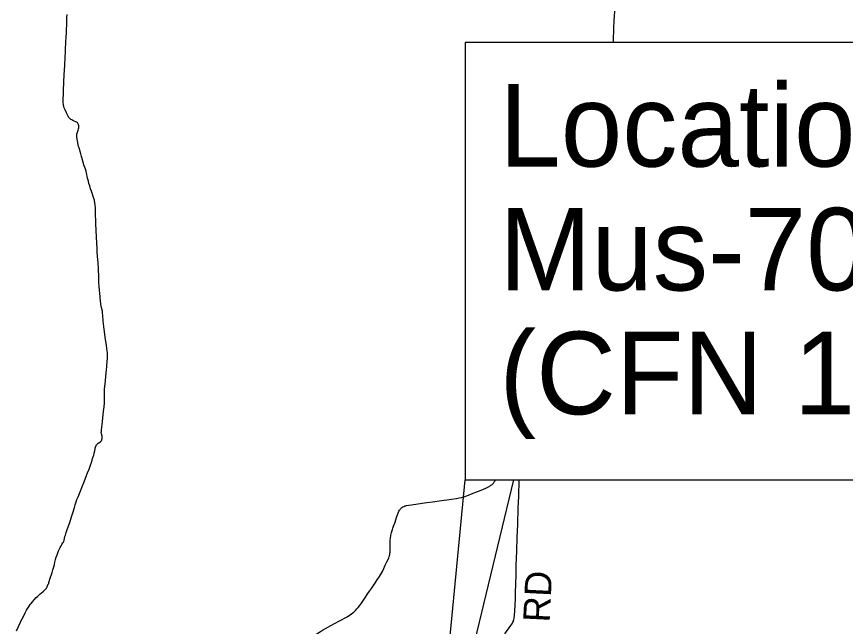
# Model space of a CAD drawing. Extents: x 1761803 to 2441803, y 509895 to 949895.
# Drawn here: x 2113045 to 2141149, y 814988 to 835674 of the extents above; entities that cross this region are included whole.
import ezdxf

# ---------------------------------------------------------------- set-up
doc = ezdxf.new("R2010")
doc.units = 0
for name, color, linetype in [('GM_X_County_Road', 7, 'Continuous'), ('GM_X_Minor_Lake', 7, 'Continuous'), ('GM_X_State_Location', 7, 'Continuous')]:
    doc.layers.add(name, color=color, linetype=linetype)

msp = doc.modelspace()

# ---------------------------------------------------------------- linework, layer by layer
at = {"layer": 'GM_X_County_Road'}
msp.add_lwpolyline([(2129600, 814737), (2129806, 815021), (2129835, 815061), (2129861, 815102), (2129876, 815131), (2129889, 815162), (2129899, 815193), (2129907, 815225), (2129916, 815273), (2129929, 815370), (2129941, 815501), (2129960, 815925), (2129967, 816089), (2129976, 816467), (2129981, 816693), (2129990, 817070), (2130007, 817544), (2130021, 818018), (2130038, 818440), (2130055, 819010), (2130065, 819195), (2130074, 819411), (2130090, 819951), (2130090, 819961)], dxfattribs=at)
at = {"layer": 'GM_X_Minor_Lake'}
for points in [[(2133281, 834796), (2133283, 834853), (2133300, 835280), (2133312, 835526), (2133327, 835852)], [(2114639, 833153), (2114640, 833174), (2114663, 833714), (2114676, 834009), (2114692, 834304), (2114699, 834464), (2114704, 834550), (2114718, 834812), (2114726, 834976), (2114733, 835123), (2114740, 835254), (2114744, 835368), (2114751, 835548), (2114754, 835646), (2114758, 835745)], [(2114248, 816818), (2114278, 816912), (2114307, 817009), (2114326, 817089), (2114347, 817171), (2114369, 817258), (2114393, 817341), (2114418, 817413), (2114442, 817481), (2114467, 817547), (2114488, 817598), (2114520, 817669), (2114552, 817726), (2114579, 817767), (2114617, 817821), (2114635, 817850), (2114644, 817874), (2114656, 817912), (2114686, 818037), (2114699, 818085), (2114727, 818171), (2114751, 818242), (2114763, 818275), (2114850, 818518), (2114906, 818705), (2114962, 818880), (2115008, 819021), (2115037, 819114), (2115069, 819218), (2115093, 819288), (2115130, 819379), (2115199, 819554), (2115281, 819758), (2115332, 819896), (2115416, 820109), (2115453, 820200), (2115502, 820322), (2115554, 820461), (2115584, 820551), (2115610, 820632), (2115624, 820679), (2115664, 820801), (2115679, 820866), (2115695, 820948), (2115705, 821004), (2115712, 821037), (2115721, 821073), (2115733, 821103), (2115740, 821118), (2115747, 821132), (2115755, 821145), (2115765, 821158), (2115775, 821170), (2115787, 821180), (2115812, 821201), (2115864, 821235), (2115889, 821254), (2115907, 821271), (2115919, 821288), (2115931, 821310), (2115937, 821331), (2115942, 821365), (2115944, 821382), (2115945, 821398), (2115945, 821415), (2115942, 821447), (2115922, 821522), (2115918, 821561), (2115919, 821600), (2115920, 821630), (2115923, 821659), (2115943, 821835), (2115955, 821949), (2115997, 822274), (2116017, 822437), (2116027, 822564), (2116028, 822645), (2116023, 822737), (2116022, 822884), (2116024, 822978), (2116028, 823043), (2116046, 823222), (2116056, 823320), (2116072, 823482), (2116094, 823694), (2116106, 823810), (2116120, 823997), (2116123, 824050), (2116125, 824066), (2116127, 824172), (2116127, 824222), (2116123, 824284), (2116119, 824327), (2116109, 824416), (2116093, 824524), (2116073, 824653), (2116049, 824801), (2116022, 824991), (2116002, 825149), (2115991, 825263), (2115981, 825348), (2115968, 825534), (2115961, 825625), (2115954, 825682), (2115937, 825765), (2115915, 825862), (2115906, 825912), (2115901, 825948), (2115895, 826013), (2115867, 826304), (2115859, 826371), (2115845, 826544), (2115838, 826636), (2115834, 826693), (2115830, 826832), (2115826, 827115), (2115824, 827179), (2115816, 827265), (2115807, 827346), (2115800, 827411), (2115778, 827692), (2115772, 827830), (2115769, 827982), (2115756, 828205), (2115730, 828641), (2115724, 829046), (2115720, 829176), (2115711, 829284), (2115703, 829347), (2115682, 829443), (2115668, 829505), (2115647, 829571), (2115605, 829689), (2115582, 829750), (2115556, 829828), (2115525, 829930), (2115500, 830011), (2115480, 830086), (2115454, 830197), (2115416, 830377), (2115401, 830434), (2115368, 830533), (2115342, 830607), (2115331, 830640), (2115261, 830896), (2115252, 830932), (2115226, 831016), (2115164, 831216), (2115149, 831270), (2115106, 831459), (2115099, 831499), (2115094, 831527), (2115088, 831578), (2115088, 831617), (2115089, 831651), (2115093, 831684), (2115101, 831723), (2115132, 831816), (2115146, 831864), (2115152, 831897), (2115154, 831913), (2115155, 831930), (2115154, 831946), (2115153, 831963), (2115151, 831980), (2115147, 831996), (2115141, 832012), (2115135, 832029), (2115126, 832050), (2115117, 832065), (2115107, 832075), (2115091, 832087), (2115056, 832107), (2115000, 832130), (2114950, 832150), (2114918, 832167), (2114888, 832186), (2114863, 832206), (2114851, 832216), (2114840, 832228), (2114830, 832240), (2114811, 832267), (2114794, 832294), (2114771, 832337), (2114735, 832411), (2114689, 832516), (2114664, 832576), (2114649, 832622), (2114641, 832653), (2114632, 832701), (2114627, 832749), (2114625, 832798), (2114625, 832863), (2114626, 832912), (2114631, 832994), (2114639, 833153)], [(2125418, 816797), (2125418, 816797), (2125449, 816855), (2125500, 816957), (2125547, 817061), (2125604, 817180), (2125639, 817254), (2125665, 817315), (2125682, 817360), (2125689, 817384), (2125695, 817404), (2125698, 817422), (2125701, 817441), (2125705, 817474), (2125707, 817503), (2125710, 817553), (2125712, 817615), (2125714, 817766), (2125714, 817865), (2125716, 817929), (2125721, 817970), (2125723, 817996), (2125735, 818060), (2125748, 818124), (2125759, 818169), (2125769, 818208), (2125791, 818276), (2125807, 818324), (2125829, 818391), (2125879, 818528), (2125905, 818606), (2125932, 818685), (2125974, 818808), (2125995, 818862), (2126011, 818900), (2126027, 818929), (2126037, 818944), (2126047, 818959), (2126061, 818976), (2126077, 818992), (2126092, 819006), (2126106, 819017), (2126119, 819026), (2126147, 819045), (2126177, 819060), (2126208, 819073), (2126219, 819076), (2126239, 819083), (2126271, 819090), (2126344, 819103), (2126441, 819117), (2126800, 819167), (2126952, 819190), (2127153, 819219), (2127456, 819260), (2127635, 819285), (2127797, 819307), (2127960, 819329), (2128057, 819346), (2128137, 819362), (2128200, 819379), (2128246, 819394), (2128368, 819441), (2128475, 819484), (2128703, 819576), (2128855, 819637), (2128974, 819686), (2129020, 819706), (2129045, 819718), (2129066, 819729), (2129086, 819740), (2129107, 819756), (2129131, 819774), (2129157, 819795), (2129179, 819817), (2129211, 819852), (2129242, 819892), (2129259, 819919), (2129276, 819947), (2129282, 819961)], [(2113045, 814840), (2113176, 815132), (2113182, 815146), (2113230, 815246), (2113309, 815395), (2113340, 815453), (2113387, 815539), (2113428, 815610), (2113471, 815679), (2113508, 815732), (2113538, 815771), (2113581, 815821), (2113646, 815894), (2113714, 815965), (2113749, 815999), (2113808, 816055), (2113845, 816088), (2113882, 816119), (2113958, 816181), (2113995, 816214), (2114018, 816238), (2114040, 816263), (2114059, 816290), (2114068, 816304), (2114083, 816333), (2114097, 816363), (2114109, 816394), (2114118, 816419), (2114122, 816427), (2114126, 816435), (2114136, 816449), (2114135, 816458), (2114135, 816466), (2114137, 816479), (2114185, 816628), (2114236, 816784), (2114248, 816818)], [(2124206, 815291), (2124254, 815319), (2124338, 815371), (2124392, 815407), (2124457, 815456), (2124495, 815488), (2124542, 815533), (2124586, 815581), (2124629, 815630), (2124669, 815682), (2124736, 815775), (2124855, 815950), (2124958, 816100), (2125013, 816181), (2125079, 816275), (2125196, 816449), (2125271, 816565), (2125351, 816684), (2125418, 816797)], [(2123866, 815110), (2123952, 815156), (2124082, 815224), (2124169, 815270), (2124206, 815291)], [(2121958, 813840), (2122042, 813912), (2122143, 813996), (2122235, 814067), (2122355, 814156), (2122474, 814244), (2122595, 814330), (2122662, 814375), (2122743, 814431), (2122853, 814502), (2122915, 814541), (2122978, 814581), (2123116, 814669), (2123227, 814740), (2123350, 814820), (2123420, 814864), (2123519, 814922), (2123706, 815024), (2123850, 815101), (2123866, 815110)]]:
    msp.add_lwpolyline(points, dxfattribs=at)
at = {"layer": 'GM_X_State_Location'}
for points in [[(2128253, 819961), (2157629, 819961), (2157629, 834796), (2128253, 834796)], [(2127176, 808660), (2128253, 819961), (2129889, 819961)]]:
    msp.add_lwpolyline(points, close=True, dxfattribs=at)

# ---------------------------------------------------------------- texts
at = {"layer": 'GM_X_County_Road'}
msp.add_text('RD', height=900, rotation=87.2056, dxfattribs=at).set_placement((2131119, 815114))
at = {"layer": 'GM_X_State_Location'}
for s, p in [('Location 14:', (2129416, 830585)), ('Mus-70-15.934', (2129416, 826385)), ('(CFN 1973448)', (2129416, 822185))]:
    msp.add_text(s, height=2800, dxfattribs=at).set_placement(p)

doc.saveas('drawing.dxf')
